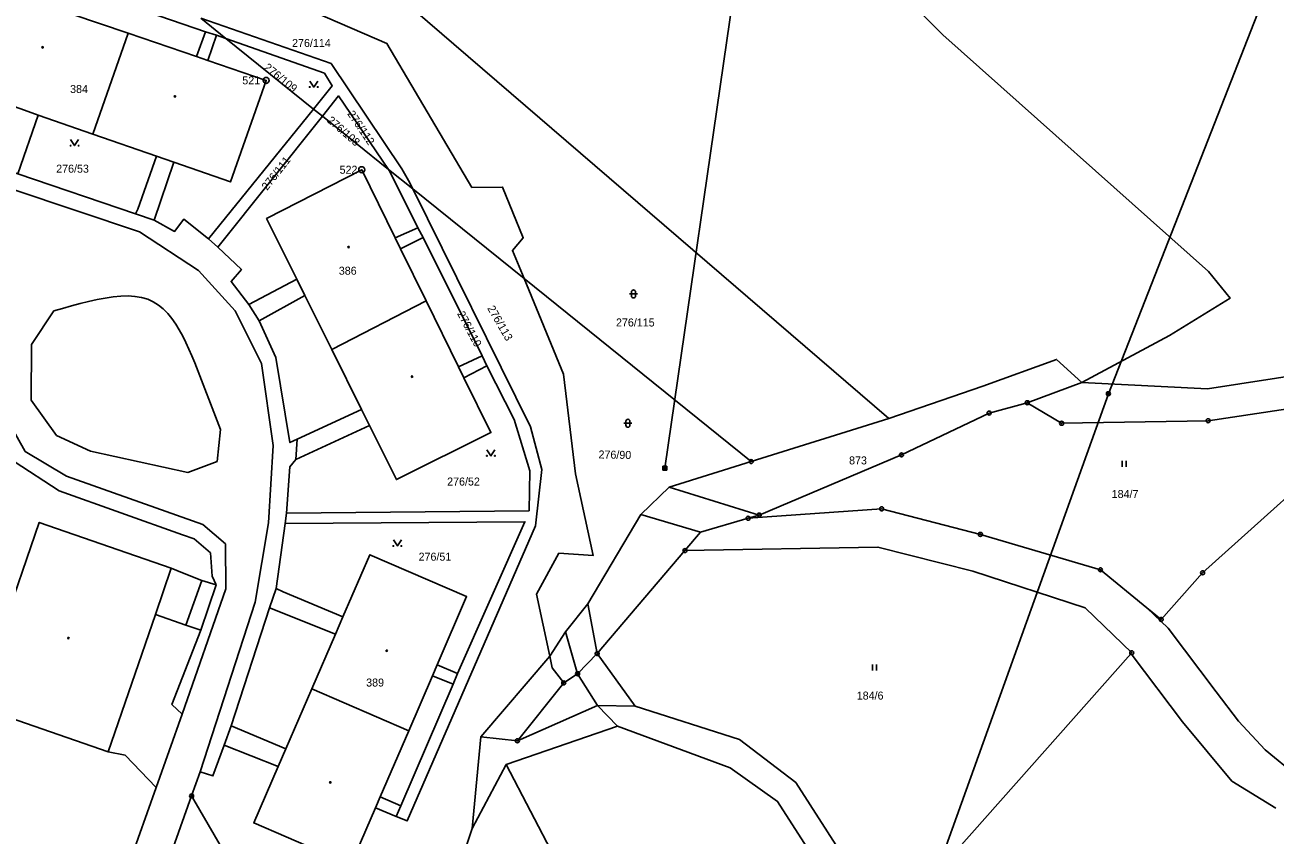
# Model space of a CAD drawing. Extents: x -745926 to -742978, y -968282 to -965689.
# Drawn here: x -744649.7 to -744493.5, y -967089.1 to -966987.9 of the extents above; entities that cross this region are included whole.
import ezdxf

# ---------------------------------------------------------------- set-up
doc = ezdxf.new("R2010")
doc.units = 0
for name, color, linetype in [('Hranice parcel', 7, 'Continuous'), ('Parcelní čísla', 7, 'Continuous'), ('Poz předměty', 7, 'Continuous'), ('Vnitřní kresba', 7, 'Continuous'), ('Značky bodu BP', 7, 'Continuous'), ('Značky budov', 7, 'Continuous'), ('Značky kultur', 7, 'Continuous')]:
    doc.layers.add(name, color=color, linetype=linetype)

msp = doc.modelspace()

# ---------------------------------------------------------------- linework, layer by layer
at = {"layer": 'Hranice parcel'}
for p, q in [((-744635.36, -966956.43), (-744541.81, -967037.05)), ((-744624.63, -966989.55), (-744627.78, -966987.01)), ((-744613.69, -966998.36), (-744624.63, -966989.55)), ((-744626.8, -967014.59), (-744613.69, -966998.36)), ((-744612.58, -966999.25), (-744625.64, -967015.6)), ((-744612.58, -966999.25), (-744613.69, -966998.36)), ((-744604.33, -967005.89), (-744612.58, -966999.25)), ((-744601.29, -967008.34), (-744604.33, -967005.89)), ((-744587.38, -967019.54), (-744601.29, -967008.34)), ((-744625.64, -967015.6), (-744626.8, -967014.59)), ((-744558.99, -967042.41), (-744587.38, -967019.54)), ((-744541.81, -967037.05), (-744558.99, -967042.41)), ((-744617.25, -967050.15), (-744617.08, -967048.87)), ((-744578.24, -967066.41), (-744567.27, -967053.53)), ((-744584.16, -967066.75), (-744592.78, -967076.83)), ((-744588.21, -967077.31), (-744582.42, -967070.07)), ((-744589.6, -967080.29), (-744575.69, -967075.49)), ((-744592.78, -967076.83), (-744593.86, -967088.29)), ((-744588.21, -967077.31), (-744592.78, -967076.83)), ((-744624.84, -967077.84), (-744618.11, -967080.52)), ((-744593.86, -967088.29), (-744589.6, -967080.29)), ((-744637.01, -967093.36), (-744633.34, -967083.14)), ((-744632.68, -967094.73), (-744628.92, -967084.21)), ((-744619.82, -967099.9), (-744628.92, -967084.21)), ((-744605.95, -967085.7), (-744603.35, -967086.76))]:
    msp.add_line(p, q, dxfattribs=at)
for points in [[(-744448.61, -966987.65), (-744463.93, -966998.96), (-744466.24, -966995.24), (-744496.79, -966958.66), (-744533.38, -966920.02), (-744545.19, -966931.03), (-744564.85, -966959.3), (-744535.05, -966989.09), (-744501.82, -967018.66), (-744499.12, -967021.98), (-744506.72, -967026.67), (-744517.65, -967032.54)], [(-744587.38, -967019.54), (-744588.83, -967016.05), (-744587.48, -967014.44), (-744590.07, -967008.1), (-744593.89, -967008.14), (-744604.51, -966990.18), (-744623.99, -966981.71), (-744624.02, -966976.6), (-744632.06, -966973.36), (-744636.07, -966978.05), (-744647.24, -966971.34)], [(-744624.63, -966989.55), (-744625.82, -966989.13), (-744627.17, -966988.69), (-744642.96, -966983.23), (-744644.23, -966982.84), (-744654.6, -966979.36), (-744663.03, -967001.61), (-744663.03, -967002.19)], [(-744641.26, -967001.49), (-744633.32, -967004.25), (-744631.15, -967005.01), (-744624.08, -967007.47), (-744619.61, -966994.77), (-744626.9, -966992.28), (-744628.31, -966991.8), (-744636.87, -966988.88), (-744643.88, -966986.49), (-744645.31, -966986), (-744654.14, -966982.99), (-744658.49, -966995.48), (-744650.28, -966998.34), (-744648.11, -966999.1), (-744641.26, -967001.49)], [(-744601.29, -967008.34), (-744601.82, -967007.28), (-744602.65, -967005.82), (-744611.5, -966992.67), (-744627.78, -966987.01)], [(-744613.69, -966998.36), (-744611.34, -966995.44), (-744612.33, -966993.86), (-744624.63, -966989.55)], [(-744604.33, -967005.89), (-744610.55, -966996.71), (-744612.58, -966999.25)], [(-744625.84, -967057.82), (-744626.36, -967056.75), (-744626.56, -967053.84), (-744628.6, -967052.05), (-744630.08, -967051.55), (-744645.48, -967046.06), (-744651.12, -967042.4), (-744654.67, -967036.55), (-744655.31, -967033.56), (-744654.02, -967022.62), (-744654.48, -967018.82), (-744657.58, -967015.44), (-744661.33, -967013.77), (-744669.74, -967010.9), (-744696.2, -967001.68), (-744699.25, -967005.14), (-744702.72, -967010.81)], [(-744663.03, -967002.19), (-744652.96, -967005.68), (-744650.65, -967006.45), (-744635.93, -967011.45), (-744633.62, -967012.26), (-744631.06, -967013.64), (-744629.91, -967012.13), (-744626.8, -967014.59)], [(-744517.65, -967032.54), (-744501.96, -967033.31), (-744472.61, -967028.79), (-744464.91, -967020.49), (-744456.81, -967003.87)], [(-744611.42, -967028.39), (-744607.69, -967035.89), (-744606.69, -967037.9), (-744603.33, -967044.67), (-744591.52, -967038.8), (-744594.89, -967031.94), (-744595.55, -967030.59), (-744599.61, -967022.32), (-744602.8, -967015.83), (-744603.47, -967014.47), (-744607.66, -967005.94), (-744619.55, -967012.05), (-744615.78, -967019.63), (-744614.76, -967021.67), (-744611.42, -967028.39)], [(-744617.08, -967048.87), (-744586.74, -967048.55), (-744586.64, -967043.56), (-744588.6, -967037.16), (-744592.01, -967030.43), (-744592.63, -967029.18), (-744600, -967014.39), (-744600.66, -967013.19), (-744604.16, -967006.15), (-744604.33, -967005.89)], [(-744603.35, -967086.76), (-744601.97, -967087.32), (-744585.93, -967050.44), (-744585.14, -967043.41), (-744586.58, -967038.07), (-744601.29, -967008.34)], [(-744625.84, -967057.82), (-744627.66, -967057.26), (-744630.07, -967056.33), (-744631.47, -967055.72), (-744647.96, -967050.01), (-744652.67, -967063.77), (-744662.77, -967060.57), (-744658.02, -967047.43), (-744671.18, -967042.61), (-744675.78, -967041.06), (-744677.43, -967045.75), (-744682.33, -967060.09), (-744691.59, -967054.68), (-744687.36, -967042.31), (-744688.22, -967042.01), (-744686.56, -967037.11), (-744685.7, -967037.41), (-744677.79, -967014.07), (-744691.08, -967009.49)], [(-744625.64, -967015.6), (-744622.69, -967018.4), (-744623.99, -967019.91), (-744621.76, -967022.78), (-744620.48, -967024.83), (-744618.4, -967029.42), (-744616.63, -967040.05), (-744615.72, -967039.63), (-744615.89, -967042.15), (-744616.65, -967043.06), (-744617.08, -967048.87)], [(-744587.38, -967019.54), (-744582.45, -967031.47), (-744580.96, -967043.95), (-744578.74, -967054.14), (-744583.03, -967053.88), (-744585.84, -967058.99), (-744584.16, -967066.75)], [(-744541.81, -967037.05), (-744530.04, -967033), (-744520.82, -967029.64), (-744517.65, -967032.54)], [(-744559.38, -967049.5), (-744557.99, -967049.1), (-744540.21, -967041.58), (-744529.26, -967036.35), (-744524.49, -967035.06), (-744520.2, -967037.63), (-744501.89, -967037.31), (-744470.62, -967032.6)], [(-744482.7, -967038.5), (-744502.57, -967056.31), (-744507.75, -967062.15), (-744509.54, -967060.69), (-744515.34, -967055.94), (-744530.35, -967051.51), (-744542.69, -967048.32), (-744559.38, -967049.5)], [(-744572.79, -967049.03), (-744569.25, -967045.61), (-744558.99, -967042.41)], [(-744584.16, -967066.75), (-744582.21, -967063.69), (-744579.39, -967060.19), (-744572.79, -967049.03)], [(-744559.38, -967049.5), (-744565.31, -967051.22), (-744567.27, -967053.53)], [(-744617.25, -967050.15), (-744618.35, -967058.29), (-744619.2, -967060.7), (-744623.98, -967075.45), (-744624.84, -967077.84)], [(-744603.35, -967086.76), (-744602.79, -967085.45), (-744596.25, -967070.25), (-744595.7, -967068.91), (-744587.28, -967049.93), (-744617.25, -967050.15)], [(-744605.95, -967085.7), (-744605.36, -967084.32), (-744601.79, -967076.05), (-744598.83, -967069.18), (-744598.23, -967067.8), (-744594.55, -967059.29), (-744606.66, -967054.05), (-744610.02, -967061.83), (-744610.95, -967063.99), (-744613.91, -967070.81), (-744617.15, -967078.3), (-744618.11, -967080.52)], [(-744567.27, -967053.53), (-744543.15, -967053.11), (-744531.29, -967056.12), (-744517.27, -967060.7), (-744511.44, -967066.31), (-744511.55, -967066.43), (-744542.16, -967100.96)], [(-744642.01, -967107.49), (-744646.82, -967105.88), (-744644.38, -967098.17), (-744690.01, -967082.29), (-744692.56, -967089.69), (-744694.24, -967089.14), (-744700.9, -967086.97), (-744702.61, -967086.38), (-744709.09, -967084.14), (-744703.71, -967069.13), (-744697.29, -967071), (-744692.99, -967058.57), (-744683.72, -967063.97), (-744686.55, -967072.36), (-744669.16, -967078.42), (-744664.11, -967064.32), (-744654.06, -967067.83), (-744655.83, -967072.99), (-744639.35, -967078.71), (-744637.23, -967079.09), (-744633.34, -967083.14)], [(-744633.34, -967083.14), (-744630.12, -967073.98), (-744631.39, -967072.78), (-744627.78, -967063.47), (-744625.84, -967057.82)], [(-744582.42, -967070.07), (-744580.68, -967068.93), (-744578.24, -967066.41)], [(-744542.16, -967100.96), (-744547.65, -967091.47), (-744553.41, -967082.53), (-744560.46, -967077.14), (-744573.49, -967072.97), (-744578.21, -967072.89), (-744588.21, -967077.31)], [(-744575.69, -967075.49), (-744561.6, -967080.68), (-744555.69, -967084.89), (-744550.18, -967093.52), (-744544.43, -967101.97), (-744553.33, -967121.21)], [(-744628.92, -967084.21), (-744627.85, -967081.2), (-744626.26, -967081.7), (-744624.84, -967077.84)], [(-744618.11, -967080.52), (-744621.15, -967087.57), (-744609.02, -967092.81), (-744605.95, -967085.7)], [(-744589.6, -967080.29), (-744577.43, -967103.6), (-744574.04, -967115.43)], [(-744593.36, -967108.69), (-744595.92, -967094.43), (-744593.86, -967088.29)]]:
    msp.add_lwpolyline(points, dxfattribs=at)
at = {"layer": 'Poz předměty'}
for p, q in [((-744556.5, -966951.63), (-744569.77, -967043.22)), ((-744489.39, -966970.29), (-744514.35, -967033.93)), ((-744514.35, -967033.93), (-744552.63, -967140.68)), ((-744570.02, -967042.97), (-744569.52, -967042.97)), ((-744570.02, -967043.47), (-744570.02, -967042.97)), ((-744570.02, -967043.07), (-744569.52, -967043.07)), ((-744570.02, -967043.17), (-744569.52, -967043.17)), ((-744569.92, -967043.47), (-744569.92, -967042.97)), ((-744569.82, -967043.47), (-744569.82, -967042.97)), ((-744569.72, -967043.47), (-744569.72, -967042.97)), ((-744569.62, -967043.47), (-744569.62, -967042.97)), ((-744569.52, -967043.47), (-744569.52, -967042.97)), ((-744570.02, -967043.27), (-744569.52, -967043.27)), ((-744570.02, -967043.37), (-744569.52, -967043.37)), ((-744570.02, -967043.47), (-744569.52, -967043.47))]:
    msp.add_line(p, q, dxfattribs=at)
for radius in [0.25, 0.2, 0.15, 0.1, 0.05]:
    msp.add_circle((-744514.35, -967033.93), radius, dxfattribs=at)
at = {"layer": 'Vnitřní kresba'}
for p, q in [((-744636.87, -966988.88), (-744641.26, -967001.49)), ((-744627.17, -966988.69), (-744628.31, -966991.8)), ((-744625.82, -966989.13), (-744626.9, -966992.28)), ((-744650.65, -967006.45), (-744648.11, -966999.1)), ((-744633.32, -967004.25), (-744635.64, -967010.88)), ((-744631.15, -967005.01), (-744633.62, -967012.26)), ((-744635.42, -967013.69), (-744651.22, -967008.4)), ((-744635.64, -967010.88), (-744635.93, -967011.45)), ((-744603.47, -967014.47), (-744600.66, -967013.19)), ((-744628.07, -967018.53), (-744635.42, -967013.69)), ((-744602.8, -967015.83), (-744600, -967014.39)), ((-744623.5, -967023.59), (-744628.07, -967018.53)), ((-744615.78, -967019.63), (-744621.76, -967022.78)), ((-744614.76, -967021.67), (-744620.48, -967024.83)), ((-744611.42, -967028.39), (-744599.61, -967022.32)), ((-744646.13, -967023.58), (-744648.92, -967027.78)), ((-744620.19, -967030.17), (-744623.5, -967023.59)), ((-744648.98, -967034.74), (-744648.92, -967027.78)), ((-744595.55, -967030.59), (-744592.63, -967029.18)), ((-744628.51, -967030.06), (-744625.33, -967038.41)), ((-744618.75, -967040.4), (-744620.19, -967030.17)), ((-744594.89, -967031.94), (-744592.01, -967030.43)), ((-744517.65, -967032.54), (-744524.49, -967035.06)), ((-744648.98, -967034.74), (-744645.79, -967039.14)), ((-744652.71, -967035.77), (-744649.72, -967041.16)), ((-744607.69, -967035.89), (-744615.72, -967039.63)), ((-744625.73, -967042.41), (-744625.33, -967038.41)), ((-744615.89, -967042.15), (-744606.69, -967037.9)), ((-744641.55, -967041.11), (-744645.79, -967039.14)), ((-744649.72, -967041.16), (-744644.55, -967044.23)), ((-744629.41, -967043.77), (-744641.55, -967041.11)), ((-744619.33, -967050.05), (-744618.75, -967040.4)), ((-744629.41, -967043.77), (-744625.73, -967042.41)), ((-744644.55, -967044.23), (-744627.51, -967050.26)), ((-744569.25, -967045.61), (-744557.99, -967049.1)), ((-744565.31, -967051.22), (-744572.79, -967049.03)), ((-744624.68, -967052.68), (-744627.51, -967050.26)), ((-744620.99, -967059.98), (-744619.33, -967050.05)), ((-744624.68, -967052.68), (-744624.63, -967058.33)), ((-744633.44, -967061.51), (-744631.47, -967055.72)), ((-744627.66, -967057.26), (-744629.64, -967062.85)), ((-744630.12, -967073.98), (-744624.63, -967058.33)), ((-744618.35, -967058.29), (-744617.5, -967058.68)), ((-744617.5, -967058.68), (-744610.02, -967061.83)), ((-744627.85, -967081.2), (-744620.99, -967059.98)), ((-744578.24, -967066.41), (-744579.39, -967060.19)), ((-744633.44, -967061.51), (-744639.35, -967078.71)), ((-744629.64, -967062.85), (-744633.44, -967061.51)), ((-744610.95, -967063.99), (-744619.2, -967060.7)), ((-744506.88, -967063.23), (-744509.54, -967060.69)), ((-744627.78, -967063.47), (-744629.64, -967062.85)), ((-744506.88, -967063.23), (-744500.9, -967071.21)), ((-744582.21, -967063.69), (-744580.68, -967068.93)), ((-744573.49, -967072.97), (-744578.24, -967066.41)), ((-744511.38, -967066.59), (-744511.55, -967066.43)), ((-744505.07, -967074.96), (-744511.38, -967066.59)), ((-744598.23, -967067.8), (-744595.7, -967068.91)), ((-744583.85, -967068.18), (-744584.16, -967066.75)), ((-744583.85, -967068.18), (-744582.42, -967070.07)), ((-744598.83, -967069.18), (-744596.25, -967070.25)), ((-744580.68, -967068.93), (-744578.21, -967072.89)), ((-744613.91, -967070.81), (-744601.79, -967076.05)), ((-744500.9, -967071.21), (-744498.11, -967074.84)), ((-744578.21, -967072.89), (-744575.69, -967075.49)), ((-744623.98, -967075.45), (-744617.15, -967078.3)), ((-744498.94, -967082.37), (-744505.07, -967074.96)), ((-744498.11, -967074.84), (-744494.77, -967078.46)), ((-744494.77, -967078.46), (-744490.8, -967081.67)), ((-744493.44, -967085.72), (-744498.94, -967082.37)), ((-744605.36, -967084.32), (-744602.79, -967085.45))]:
    msp.add_line(p, q, dxfattribs=at)
msp.add_lwpolyline([(-744646.13, -967023.58), (-744645.04, -967023.27), (-744643.94, -967022.96), (-744642.86, -967022.67), (-744641.8, -967022.4), (-744640.74, -967022.17), (-744639.72, -967021.98), (-744638.74, -967021.83), (-744637.77, -967021.74), (-744636.86, -967021.72), (-744636, -967021.77), (-744635.17, -967021.91), (-744634.41, -967022.13), (-744633.71, -967022.45), (-744633.05, -967022.86), (-744632.46, -967023.34), (-744631.91, -967023.9), (-744631.39, -967024.53), (-744630.91, -967025.22), (-744630.47, -967025.95), (-744630.04, -967026.72), (-744629.64, -967027.53), (-744629.26, -967028.35), (-744628.88, -967029.21), (-744628.51, -967030.06)], dxfattribs=at)
at = {"layer": 'Značky bodu BP'}
for centre, radius in [((-744619.61, -966994.77), 0.375), ((-744619.61, -966994.77), 0.015), ((-744607.66, -967005.94), 0.375), ((-744607.66, -967005.94), 0.015), ((-744524.49, -967035.06), 0.25), ((-744524.49, -967035.06), 0.0152), ((-744529.26, -967036.35), 0.25), ((-744529.26, -967036.35), 0.0152), ((-744520.2, -967037.63), 0.25), ((-744520.2, -967037.63), 0.0152), ((-744501.89, -967037.31), 0.25), ((-744501.89, -967037.31), 0.0152), ((-744540.21, -967041.58), 0.25), ((-744540.21, -967041.58), 0.0152), ((-744558.99, -967042.41), 0.25), ((-744558.99, -967042.41), 0.0152), ((-744559.38, -967049.5), 0.25), ((-744559.38, -967049.5), 0.0152), ((-744557.99, -967049.1), 0.25), ((-744557.99, -967049.1), 0.0152), ((-744542.69, -967048.32), 0.25), ((-744542.69, -967048.32), 0.0152), ((-744530.35, -967051.51), 0.25), ((-744530.35, -967051.51), 0.0152), ((-744567.27, -967053.53), 0.25), ((-744567.27, -967053.53), 0.0152), ((-744515.34, -967055.94), 0.25), ((-744515.34, -967055.94), 0.0152), ((-744502.57, -967056.31), 0.25), ((-744502.57, -967056.31), 0.0152), ((-744507.75, -967062.15), 0.25), ((-744507.75, -967062.15), 0.0152), ((-744578.24, -967066.41), 0.25), ((-744578.24, -967066.41), 0.0152), ((-744511.44, -967066.31), 0.25), ((-744511.44, -967066.31), 0.0152), ((-744582.42, -967070.07), 0.25), ((-744580.68, -967068.93), 0.25), ((-744580.68, -967068.93), 0.0152), ((-744582.42, -967070.07), 0.0152), ((-744588.21, -967077.31), 0.25), ((-744588.21, -967077.31), 0.0152), ((-744628.92, -967084.21), 0.25), ((-744628.92, -967084.21), 0.0152)]:
    msp.add_circle(centre, radius, dxfattribs=at)
at = {"layer": 'Značky budov'}
for centre in [(-744647.55, -966990.64), (-744631.01, -966996.77), (-744609.31, -967015.61), (-744601.37, -967031.8), (-744644.32, -967064.47), (-744604.53, -967066.06), (-744611.59, -967082.51)]:
    msp.add_circle(centre, 0.0875, dxfattribs=at)
at = {"layer": 'Značky kultur'}
for p, q in [((-744573.95, -967021.21), (-744573.95, -967021.71)), ((-744573.45, -967021.71), (-744573.45, -967021.21)), ((-744574.2, -967021.46), (-744573.2, -967021.46)), ((-744574.9, -967037.63), (-744573.9, -967037.63)), ((-744574.65, -967037.38), (-744574.65, -967037.88)), ((-744574.15, -967037.88), (-744574.15, -967037.38)), ((-744512.65, -967043.06), (-744512.65, -967042.31)), ((-744512.15, -967043.06), (-744512.15, -967042.31)), ((-744543.83, -967068.52), (-744543.83, -967067.77)), ((-744543.33, -967068.52), (-744543.33, -967067.77))]:
    msp.add_line(p, q, dxfattribs=at)
for points in [[(-744614.16, -966994.85), (-744613.66, -966995.6), (-744613.16, -966994.85)], [(-744644.04, -967002.18), (-744643.54, -967002.93), (-744643.04, -967002.18)], [(-744592.02, -967040.95), (-744591.52, -967041.7), (-744591.02, -967040.95)], [(-744603.71, -967052.21), (-744603.21, -967052.96), (-744602.71, -967052.21)]]:
    msp.add_lwpolyline(points, dxfattribs=at)
for centre in [(-744614.16, -966995.6), (-744613.16, -966995.6), (-744644.04, -967002.93), (-744643.04, -967002.93), (-744592.02, -967041.7), (-744591.02, -967041.7), (-744603.71, -967052.96), (-744602.71, -967052.96)]:
    msp.add_circle(centre, 0.05, dxfattribs=at)
for centre, start, end in [((-744573.7, -967021.21), 0, 180), ((-744573.7, -967021.71), 180, 359.9879), ((-744574.4, -967037.38), 0, 180), ((-744574.4, -967037.88), 180, 359.9879)]:
    msp.add_arc(centre, 0.25, start, end, dxfattribs=at)

# ---------------------------------------------------------------- texts
at = {"layer": 'Parcelní čísla'}
for s, p in [('276/114', (-744616.37, -966990.6)), ('384', (-744644.11, -966996.35)), ('276/53', (-744645.85, -967006.31)), ('386', (-744610.53, -967019.06)), ('276/115', (-744575.89, -967025.53)), ('873', (-744546.76, -967042.77)), ('276/52', (-744596.99, -967045.41)), ('184/7', (-744513.94, -967046.97)), ('276/51', (-744600.56, -967054.8)), ('389', (-744607.11, -967070.53)), ('184/6', (-744545.8, -967072.16))]:
    msp.add_text(s, height=1, dxfattribs=at).set_placement(p)
for s, rotation, p in [('276/109', 321, (-744619.98, -966993.31)), ('276/108', 319, (-744612.08, -966999.9)), ('276/112', 304, (-744609.51, -966998.95)), ('276/111', 52, (-744619.48, -967008.59)), ('276/113', 300, (-744592.01, -967023.25)), ('276/110', 298, (-744595.77, -967023.93)), ('276/90', 359, (-744578.08, -967042.02))]:
    msp.add_text(s, height=1, rotation=rotation, dxfattribs=at).set_placement(p)
at = {"layer": 'Značky bodu BP'}
for s, p in [('521', (-744622.59, -966995.27)), ('522', (-744610.43, -967006.44))]:
    msp.add_text(s, height=1, dxfattribs=at).set_placement(p)

doc.saveas('drawing.dxf')
